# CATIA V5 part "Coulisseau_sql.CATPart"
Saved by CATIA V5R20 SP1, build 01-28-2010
Part number: Coulisseau sql
Publications: "Droite.1", "Point.2", "Droite.2", "Droite.3", "Cp"
Bounding box of the stored display mesh (mm): x -20 to 20, y -10 to 10, z -12 to 0
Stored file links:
  C:\Documents and Settings\pschann\Bureau\IAO\Coulisseau_sql.CATPart
  J:\Projet\CAO\Projet IAO.CATProduct
  C:\Documents and Settings\pschann\Bureau\IAO\Bielle_BC_sql.CATPart
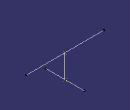
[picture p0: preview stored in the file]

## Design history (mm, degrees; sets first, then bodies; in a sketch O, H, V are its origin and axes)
External parameters (linked from other documents)
  External.a = 12 mm
Set1
  Line1: type Normal, RefPoint Point2, RefSkin yz-plane, Start -20, End 20
  Point1: type OnPlane, Support yz-plane, RefPoint Point2, H 0, V -12 {= -External.a}, Direction (0, 1, 0)
  Line2: type PtPt, FirstPoint Point2, SecondPoint Point1
  Line3: type Normal, RefPoint Point1, RefSkin zx-plane, Start -10, End 10
  Point2 "Cp": type OnPlane, Support yz-plane, H 0, V 0, Direction (0, 1, 0)
Body1 (main body)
